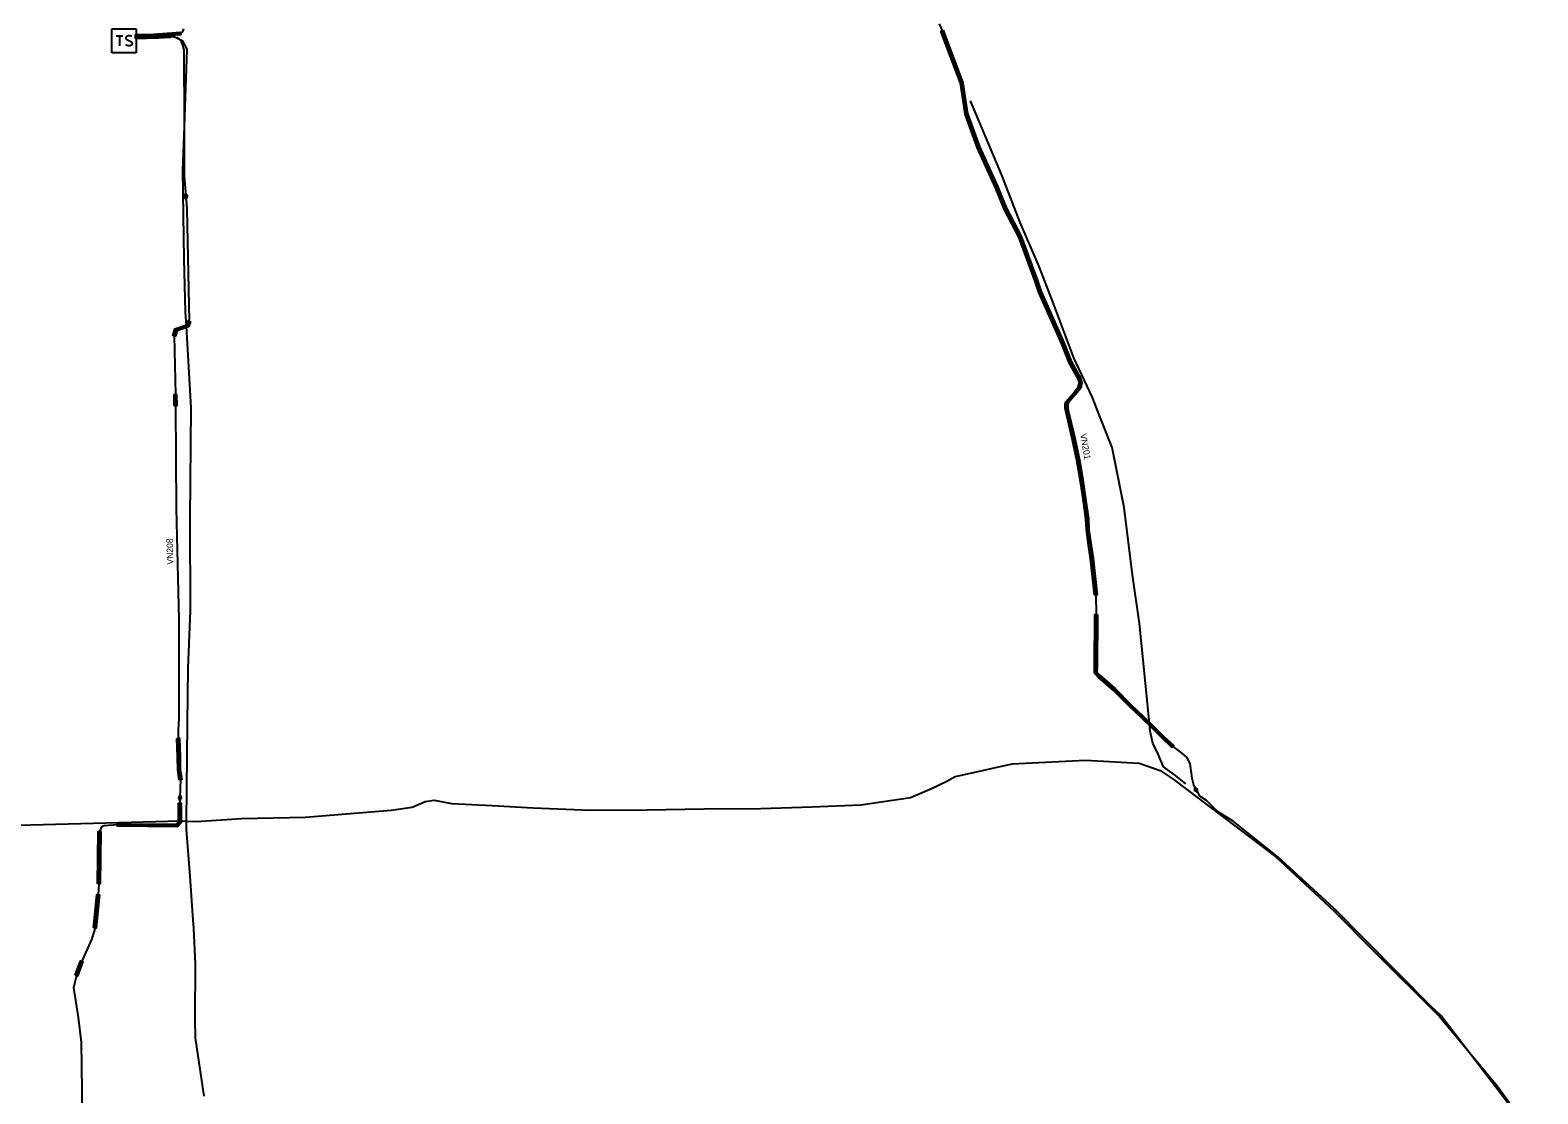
# Model space of a CAD drawing. Extents: x -643811 to -636362, y -1117362 to -1108614.
# Drawn here: x -641467.6 to -641232.4, y -1114563.5 to -1114397.7 of the extents above; entities that cross this region are included whole.
import ezdxf

# ---------------------------------------------------------------- set-up
doc = ezdxf.new("R2010")
doc.units = 0
for name, color, linetype in [('19', 7, 'Continuous'), ('20', 7, 'Continuous'), ('25', 7, 'Continuous'), ('5', 7, 'Continuous'), ('7', 7, 'Continuous'), ('9', 7, 'Continuous')]:
    doc.layers.add(name, color=color, linetype=linetype)

# ---------------------------------------------------------------- blocks, each defined once
blk = doc.blocks.new('VN870')
at = {"layer": '19'}
for points in [[(0, -0.25), (0.5, 0), (0, 0.25), (-0.5, 0), (0, -0.25)], [(0.37, 0), (0, 0.19), (-0.36, 0), (0, -0.19), (0.37, 0)], [(0.24, 0), (0, 0.12), (-0.25, 0), (0, -0.12), (0.24, 0)], [(0.12, 0), (0, 0.06), (-0.13, 0), (0, -0.06), (0.12, 0)]]:
    blk.add_lwpolyline(points, dxfattribs=at)
blk = doc.blocks.new('VN640')
at = {"layer": '25'}
for points in [[(-1.89, 1.89), (1.89, 1.89)], [(-1.89, -1.89), (-1.89, 1.89)], [(-1.26, 0.79), (-0.22, 0.79)], [(-0.73, 0.79), (-0.73, -0.79)], [(1.2, 0.66), (0.94, 0.79), (0.66, 0.79), (0.41, 0.66), (0.28, 0.47), (0.28, 0.41), (0.41, 0.22), (1.13, -0.16), (1.26, -0.32), (1.26, -0.47), (1.13, -0.66), (0.91, -0.79), (0.63, -0.79), (0.5, -0.73), (0.28, -0.6)], [(1.89, 1.89), (1.89, -1.89)], [(1.89, -1.89), (-1.89, -1.89)]]:
    blk.add_lwpolyline(points, dxfattribs=at)

msp = doc.modelspace()

# ---------------------------------------------------------------- linework, layer by layer
at = {"layer": '20'}
for points in [[(-641451.11, -1114398.75), (-641451.12, -1114398.75), (-641451.12, -1114398.35), (-641449.06, -1114398.31), (-641444.07, -1114397.96), (-641444.05, -1114398.36), (-641445.68, -1114398.47), (-641449.04, -1114398.71)], [(-641451.11, -1114398.57), (-641449.37, -1114398.54), (-641447.55, -1114398.48), (-641445.68, -1114398.38), (-641445.68, -1114398.47), (-641445.66, -1114398.78), (-641447.53, -1114398.88), (-641449.37, -1114398.94), (-641451.11, -1114398.97), (-641451.11, -1114398.75)], [(-641325.15, -1114397.66), (-641324.8, -1114398.65), (-641322.09, -1114405.84), (-641321.36, -1114410.64), (-641319.48, -1114415.81), (-641316.63, -1114422.08), (-641315.27, -1114425.4), (-641313, -1114429.77), (-641310.43, -1114436.68), (-641309.88, -1114438.4), (-641306.27, -1114446.45), (-641305.13, -1114449.36), (-641303.67, -1114451.99), (-641303.55, -1114452.65), (-641303.7, -1114453.46), (-641304.55, -1114454.51), (-641305.28, -1114455.32), (-641305.68, -1114455.82), (-641305.73, -1114456.15), (-641305.73, -1114456.56), (-641305.65, -1114456.95), (-641304.67, -1114461), (-641303.89, -1114464.66), (-641303.37, -1114467.7), (-641303.04, -1114469.99), (-641302.51, -1114473.8), (-641302.42, -1114475.53), (-641302.07, -1114477.96), (-641301.77, -1114479.99), (-641301.15, -1114485.67), (-641301.55, -1114485.71), (-641302.17, -1114480.05), (-641302.47, -1114478.02), (-641302.82, -1114475.57), (-641302.91, -1114473.84), (-641303.44, -1114470.05), (-641303.77, -1114467.76), (-641304.29, -1114464.74), (-641305.07, -1114461.08), (-641306.03, -1114457.03), (-641306.13, -1114456.6), (-641306.13, -1114456.11), (-641306.06, -1114455.66), (-641305.58, -1114455.06), (-641304.85, -1114454.25), (-641304.08, -1114453.28), (-641303.95, -1114452.65), (-641304.05, -1114452.13), (-641305.49, -1114449.54), (-641306.63, -1114446.61), (-641310.26, -1114438.54), (-641310.81, -1114436.82), (-641313.36, -1114429.93), (-641315.63, -1114425.56), (-641316.99, -1114422.24), (-641319.86, -1114415.97), (-641321.74, -1114410.74), (-641322.47, -1114405.94), (-641325.18, -1114398.79), (-641325.53, -1114397.8)], [(-641444.98, -1114444.24), (-641443.18, -1114443.57), (-641442.92, -1114442.95), (-641442.56, -1114443.11), (-641442.88, -1114443.89), (-641444.66, -1114444.54), (-641444.91, -1114445.38), (-641445.29, -1114445.26)], [(-641445.11, -1114456.22), (-641445.12, -1114454.45), (-641444.72, -1114454.45), (-641444.71, -1114456.22)], [(-641301.11, -1114488.74), (-641301.14, -1114496.91), (-641301.18, -1114497.74), (-641300.71, -1114498.23), (-641298.32, -1114500.28), (-641295.84, -1114502.83), (-641293.91, -1114504.63), (-641292.2, -1114506.32), (-641290.73, -1114507.75), (-641289.21, -1114509.18), (-641289.49, -1114509.48), (-641291.01, -1114508.03), (-641292.48, -1114506.6), (-641294.19, -1114504.91), (-641296.12, -1114503.11), (-641298.6, -1114500.58), (-641300.99, -1114498.52), (-641301.58, -1114497.9), (-641301.54, -1114496.91), (-641301.51, -1114488.74)], [(-641444.69, -1114508.06), (-641444.29, -1114508.04), (-641444.17, -1114510.96), (-641444.37, -1114510.97), (-641444.57, -1114510.98)], [(-641444.37, -1114510.97), (-641444.17, -1114510.97), (-641444.15, -1114512.98), (-641443.92, -1114514.47), (-641444.32, -1114514.53), (-641444.55, -1114513.02), (-641444.57, -1114510.98), (-641444.57, -1114510.97)], [(-641453.95, -1114521.37), (-641444.77, -1114521.45), (-641444.42, -1114521.07), (-641444.42, -1114518.18), (-641444.02, -1114518.18), (-641444.02, -1114521.23), (-641444.59, -1114521.85), (-641453.95, -1114521.77)], [(-641457.04, -1114530.72), (-641456.96, -1114522.58), (-641456.56, -1114522.58), (-641456.64, -1114530.72)], [(-641457.68, -1114537.6), (-641457.16, -1114532.4), (-641456.76, -1114532.44), (-641457.28, -1114537.64)], [(-641460.54, -1114545), (-641459.71, -1114542.73), (-641459.33, -1114542.87), (-641460.16, -1114545.14)]]:
    msp.add_lwpolyline(points, close=True, dxfattribs=at)
at = {"layer": '5'}
for points in [[(-641325.81, -1114396.67), (-641325.34, -1114397.73), (-641324.99, -1114398.72), (-641322.28, -1114405.89), (-641321.55, -1114410.69), (-641319.67, -1114415.89), (-641316.81, -1114422.16), (-641315.45, -1114425.48), (-641313.18, -1114429.85), (-641310.62, -1114436.75), (-641310.07, -1114438.47), (-641306.45, -1114446.53), (-641305.31, -1114449.45), (-641303.86, -1114452.06), (-641303.75, -1114452.65), (-641303.89, -1114453.37), (-641304.7, -1114454.38), (-641305.43, -1114455.19), (-641305.87, -1114455.74), (-641305.93, -1114456.13), (-641305.93, -1114456.58), (-641305.84, -1114456.99), (-641304.87, -1114461.04), (-641304.09, -1114464.7), (-641303.57, -1114467.73), (-641303.24, -1114470.02), (-641302.71, -1114473.82), (-641302.62, -1114475.55), (-641302.27, -1114477.99), (-641301.97, -1114480.02), (-641301.35, -1114485.69), (-641301.31, -1114488.74), (-641301.34, -1114496.91), (-641301.38, -1114497.82), (-641300.85, -1114498.38), (-641298.46, -1114500.43), (-641295.98, -1114502.97), (-641294.05, -1114504.77), (-641292.98, -1114505.82), (-641292.34, -1114506.46), (-641290.87, -1114507.89), (-641289.35, -1114509.33), (-641288.1, -1114510.26), (-641287.15, -1114511.05), (-641286.7, -1114512.03), (-641286.53, -1114513.13), (-641286.39, -1114514.26), (-641286.13, -1114515.31), (-641285.73, -1114516.08)], [(-641451.11, -1114398.77), (-641449.37, -1114398.74), (-641447.54, -1114398.68), (-641445.67, -1114398.58), (-641444.87, -1114398.74), (-641444.57, -1114398.8), (-641444.35, -1114399.01), (-641444.13, -1114399.23), (-641443.83, -1114399.82), (-641443.61, -1114400.78), (-641443.56, -1114412.24), (-641443.56, -1114412.66), (-641443.54, -1114420.37), (-641443.27, -1114423.58), (-641443.11, -1114425.5), (-641442.74, -1114443.03), (-641443.03, -1114443.73), (-641443.25, -1114443.81), (-641444.82, -1114444.39), (-641445.1, -1114445.32), (-641444.92, -1114454.45), (-641444.91, -1114456.22), (-641444.77, -1114472.21), (-641444.39, -1114489.51), (-641444.39, -1114504.9), (-641444.47, -1114506.81), (-641444.49, -1114508.05), (-641444.37, -1114510.97), (-641444.35, -1114513), (-641444.12, -1114514.5), (-641444.2, -1114517.35), (-641444.22, -1114518.18), (-641444.22, -1114520.94), (-641444.22, -1114521.15), (-641444.68, -1114521.65), (-641453.95, -1114521.57), (-641456, -1114521.71), (-641456.44, -1114521.86), (-641456.76, -1114522.58), (-641456.84, -1114530.72), (-641456.96, -1114532.42), (-641457.48, -1114537.62), (-641457.52, -1114537.99), (-641457.99, -1114539.42), (-641459.52, -1114542.8), (-641460.35, -1114545.07), (-641460.8, -1114546.93), (-641460.1, -1114551.57), (-641459.61, -1114555.42), (-641459.44, -1114566.75)], [(-641443.63, -1114397.46), (-641443.8, -1114397.91), (-641444.06, -1114398.16), (-641449.05, -1114398.51), (-641451.12, -1114398.55)], [(-641469.5, -1114521.61), (-641451.81, -1114521.13), (-641444.22, -1114520.94), (-641444.21, -1114520.94), (-641443.22, -1114520.98), (-641441.64, -1114521.04), (-641434.58, -1114520.57), (-641424.64, -1114520.35), (-641411.24, -1114519.24), (-641407.96, -1114518.79), (-641405.96, -1114517.93), (-641404.54, -1114517.7), (-641401.83, -1114518.23), (-641395.52, -1114518.52), (-641389.13, -1114518.91), (-641380.18, -1114519.24), (-641371.34, -1114519.23), (-641362.42, -1114519.03), (-641353.59, -1114519), (-641345.66, -1114518.76), (-641338.01, -1114518.41), (-641330.26, -1114517.26), (-641327, -1114515.89), (-641324.6, -1114514.74), (-641323.31, -1114514.02), (-641321.83, -1114513.71), (-641314.41, -1114512.01), (-641302.94, -1114511.48), (-641294.59, -1114511.95), (-641291.34, -1114513.09), (-641289.3, -1114514.41), (-641273.26, -1114526.54), (-641264.21, -1114534.96), (-641258.08, -1114541.15), (-641247.76, -1114551.44), (-641243.61, -1114556.4), (-641238.73, -1114562.23), (-641232.68, -1114570.58)], [(-641232.41, -1114571), (-641243.61, -1114556.4), (-641247.56, -1114551.25), (-641249.13, -1114549.75), (-641264.24, -1114534.56), (-641272.89, -1114526.59), (-641279.95, -1114520.99), (-641282.35, -1114519.44), (-641284.09, -1114517.77), (-641285.12, -1114517.08), (-641285.39, -1114516.58), (-641285.73, -1114516.08)]]:
    msp.add_lwpolyline(points, dxfattribs=at)
at = {"layer": '9'}
for points in [[(-641445.71, -1114398.3), (-641444.87, -1114398.74), (-641444.35, -1114399.01), (-641443.85, -1114399.28), (-641443.12, -1114400.6), (-641443.56, -1114412.66), (-641443.81, -1114419.54), (-641443.62, -1114433.36), (-641443.39, -1114441.54), (-641443.25, -1114443.81), (-641442.5, -1114456.53), (-641442.68, -1114473.76), (-641442.59, -1114488.13), (-641442.98, -1114497.14), (-641443.09, -1114505.73), (-641443.22, -1114520.98), (-641443.23, -1114522.25), (-641442.65, -1114529.54), (-641442.24, -1114535.66), (-641442.08, -1114537.71), (-641441.85, -1114543.22), (-641441.87, -1114551.86), (-641441.85, -1114554.75), (-641440.47, -1114563.83)], [(-641287.32, -1114515.17), (-641288.94, -1114513.86), (-641290.8, -1114512.5), (-641291.61, -1114510.51), (-641292.48, -1114508.81), (-641292.87, -1114506.96), (-641292.98, -1114505.82), (-641293.57, -1114499.99), (-641294.54, -1114490.15), (-641295.65, -1114482.56), (-641296.94, -1114472.06), (-641298.82, -1114462.7), (-641300.64, -1114458.16), (-641301.88, -1114454.9), (-641304.8, -1114448.72), (-641308.08, -1114440.01), (-641310.17, -1114434.48), (-641313.16, -1114427.66), (-641316, -1114420.25), (-641320.89, -1114408.65)]]:
    msp.add_lwpolyline(points, dxfattribs=at)

# ---------------------------------------------------------------- block references
at = {"layer": '19'}
for p, rotation in [((-641443.27, -1114423.58), -85.00000000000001), ((-641285.73, -1114516.08), 117.99999999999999), ((-641444.2, -1114517.35), 89)]:
    msp.add_blockref('VN870', p, dxfattribs=dict(at, rotation=rotation))
at = {"layer": '25'}
msp.add_blockref('VN640', (-641452.91, -1114399.31), dxfattribs=at)

# ---------------------------------------------------------------- texts
at = {"layer": '7'}
for s, rotation, p in [('VN201', 279.7381, (-641303.8, -1114460.65)), ('VN208', 91.2583, (-641445.23, -1114480.95))]:
    msp.add_text(s, height=0.994, rotation=rotation, dxfattribs=at).set_placement(p)

doc.saveas('drawing.dxf')
